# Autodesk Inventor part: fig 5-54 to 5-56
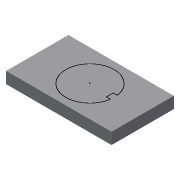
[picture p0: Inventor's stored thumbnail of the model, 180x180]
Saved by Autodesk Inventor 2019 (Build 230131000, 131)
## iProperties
Created: 2005-12
Part Number: fig 5-54 to 5-56
Document SubType Name: Modeling
Designer: CADCIM
Density: 1 g/cm^3
Material: Generic
Appearance: Default
Author: CADCIM
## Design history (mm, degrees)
sketch "Sketch1"
  geometry: L1 (-47.674, -20.831)-(44.057, -20.831); L2 (44.057, -20.831)-(44.057, 33.398); L3 (44.057, 33.398)-(-47.674, 33.398); L4 (-47.674, 33.398)-(-47.674, -20.831)
  constraints: 8 end point, 2 parallel, 1 horizontal, 1 perpendicular
extrude "Extrusion1" new body sketch "Sketch1" distance "d0" = 10; taper "d1" = 0 deg
sketch "Sketch2"
  geometry: L1 (15.359, 9.199)-(18.885, 9.199); L2 (18.885, 3.199)-(15.359, 3.199); L3 (15.359, 3.199)-(15.359, 9.199); A1 r 20.978 centre (-1.877, 6.199) between (18.885, 9.199) and (18.885, 3.199)
  constraints: 6 end point, 2 parallel, 2 point on circle, 1 centre point, 1 horizontal, 1 vertical
body "Solid1"
